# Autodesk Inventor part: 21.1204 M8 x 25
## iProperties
Created: 2006-02
Part Number: 21.1204 M8 x 25
Material: Steel, Mild
Description: Cylinder Head Cap Screw
Document SubType Name: Modeling
Standard: DIN 7984
Designer: Andy Moles
Standards Organization: DIN
Language: en-US
Size Designation: M8 x 25
Categories: <MemberInstance><Categories><Category DisplayName="Fasteners" InternalName="e4da775c-781d-43d5-af7c-5136215cf5a6" Mnemonic="FSTN"><Category DisplayName="Bolts"
Density: 7.86 g/cm^3
Mass: 14.2385 g
Surface Area: 11.4333 cm^2
Volume: 1.81151 cm^3
Author: Andy Moles
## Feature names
1. Body [Revolution]
2. Slot [Extrusion]
3. Fillet1
4. Chamfer1
